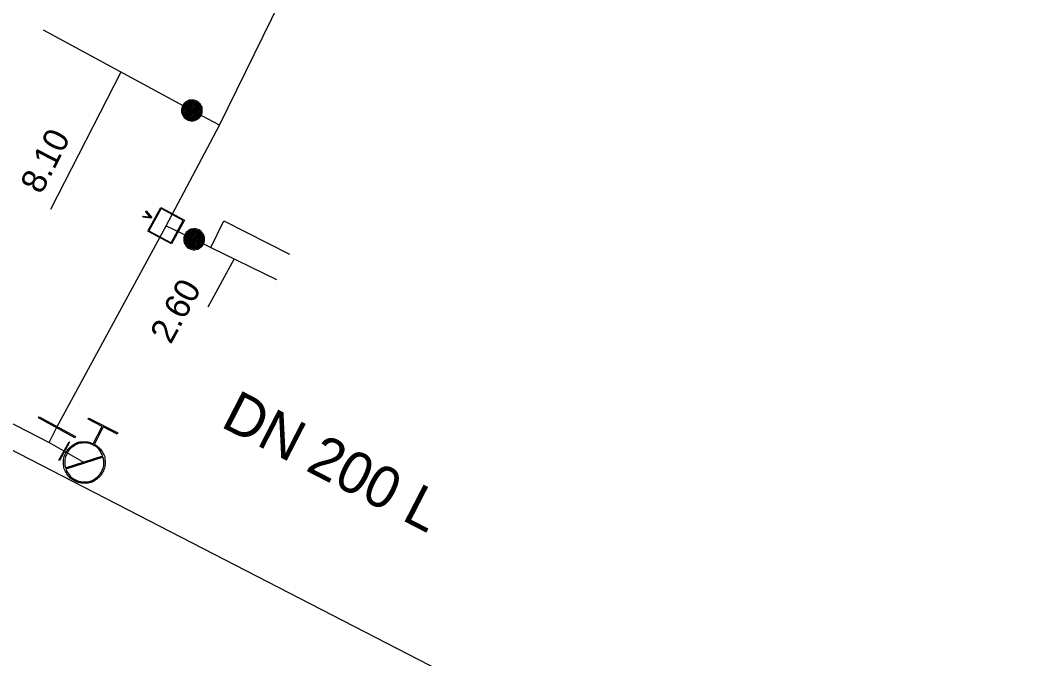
# Model space of a CAD drawing. Extents: x -820257 to -819974, y -1070894 to -1070484.
# Drawn here: x -820080.47 to -820031.98, y -1070577.38 to -1070546.62 of the extents above; entities that cross this region are included whole.
import ezdxf

# ---------------------------------------------------------------- set-up
doc = ezdxf.new("R2010")
doc.units = 0
for name, color, linetype in [('Hyd-odbočka', 7, 'Continuous'), ('Hyd-šoupě', 7, 'Continuous'), ('Hydrant', 7, 'Continuous'), ('Oměrka vodovodu', 7, 'Continuous'), ('Oměrka-text', 7, 'Continuous'), ('Přípojka vodovodu', 7, 'Continuous'), ('Přípojkový uzávěr', 7, 'Continuous'), ('Roz-řad', 7, 'Continuous'), ('Roz-řad-popis základní', 7, 'Continuous'), ('Řad-šoupě', 7, 'Continuous'), ('Šachta vodovodní', 7, 'Continuous')]:
    doc.layers.add(name, color=color, linetype=linetype)

msp = doc.modelspace()

# ---------------------------------------------------------------- linework, layer by layer
at = {"layer": 'Hyd-odbočka'}
msp.add_line((-820079.076, -1070566.966), (-820077.384, -1070567.92), dxfattribs=at)
at = {"layer": 'Hyd-šoupě'}
msp.add_lwpolyline([(-820078.091, -1070566.947), (-820078.582, -1070567.818), (-820078.609, -1070567.803), (-820078.118, -1070566.932), (-820078.091, -1070566.947)], dxfattribs=at)
at = {"layer": 'Hydrant'}
for points in [[(-820076.954, -1070567.017), (-820076.524, -1070566.183), (-820077.191, -1070565.84), (-820077.163, -1070565.784), (-820075.773, -1070566.499), (-820075.802, -1070566.555), (-820076.469, -1070566.212), (-820076.898, -1070567.045)], [(-820078.287, -1070568.177), (-820076.498, -1070567.605)], [(-820076.48, -1070567.663), (-820078.27, -1070568.237)]]:
    msp.add_lwpolyline(points, dxfattribs=at)
for points in [[(-820076.898, -1070567.045), (-820076.691, -1070567.16), (-820076.547, -1070567.371), (-820076.394, -1070567.595), (-820076.385, -1070567.87), (-820076.375, -1070568.145), (-820076.495, -1070568.378), (-820076.613, -1070568.609), (-820076.84, -1070568.76), (-820077.066, -1070568.912), (-820077.338, -1070568.92), (-820077.61, -1070568.928), (-820077.841, -1070568.809), (-820078.072, -1070568.69), (-820078.224, -1070568.464), (-820078.375, -1070568.238), (-820078.383, -1070567.965), (-820078.392, -1070567.693), (-820078.273, -1070567.462), (-820078.153, -1070567.229), (-820077.923, -1070567.078), (-820077.693, -1070566.926), (-820077.422, -1070566.92), (-820077.169, -1070566.914), (-820076.954, -1070567.017)], [(-820076.498, -1070567.605), (-820076.537, -1070567.499), (-820076.6, -1070567.405), (-820076.744, -1070567.195), (-820076.954, -1070567.086), (-820077.165, -1070566.978), (-820077.42, -1070566.983), (-820077.675, -1070566.988), (-820077.89, -1070567.13), (-820078.104, -1070567.272), (-820078.217, -1070567.491), (-820078.329, -1070567.708), (-820078.32, -1070567.963), (-820078.317, -1070568.074), (-820078.287, -1070568.177)], [(-820078.27, -1070568.237), (-820078.233, -1070568.337), (-820078.171, -1070568.429), (-820078.03, -1070568.642), (-820077.813, -1070568.753), (-820077.596, -1070568.865), (-820077.34, -1070568.857), (-820077.085, -1070568.849), (-820076.873, -1070568.708), (-820076.662, -1070568.566), (-820076.55, -1070568.349), (-820076.437, -1070568.13), (-820076.447, -1070567.873), (-820076.452, -1070567.762), (-820076.48, -1070567.663)]]:
    msp.add_open_spline(points, degree=3, dxfattribs=at)
at = {"layer": 'Oměrka vodovodu'}
for p, q in [((-820075.62, -1070549.122), (-820079.012, -1070555.738)), ((-820070.162, -1070558.11), (-820071.44, -1070560.435))]:
    msp.add_line(p, q, dxfattribs=at)
at = {"layer": 'Přípojka vodovodu'}
for p, q in [((-820071.289, -1070557.564), (-820070.668, -1070556.285)), ((-820070.668, -1070556.285), (-820067.503, -1070557.894))]:
    msp.add_line(p, q, dxfattribs=at)
for points in [[(-820070.878, -1070551.68), (-820072.198, -1070550.968), (-820079.355, -1070547.107)], [(-820073.442, -1070556.519), (-820072.092, -1070557.174), (-820071.289, -1070557.564), (-820068.118, -1070559.102)]]:
    msp.add_lwpolyline(points, dxfattribs=at)
at = {"layer": 'Přípojkový uzávěr'}
for points in [[(-820071.962, -1070550.528), (-820071.851, -1070550.588), (-820071.776, -1070550.701), (-820071.701, -1070550.815), (-820071.699, -1070550.953), (-820071.697, -1070551.091), (-820071.759, -1070551.206), (-820071.82, -1070551.32), (-820071.935, -1070551.394), (-820072.049, -1070551.467), (-820072.185, -1070551.469), (-820072.322, -1070551.47), (-820072.436, -1070551.408), (-820072.55, -1070551.347), (-820072.624, -1070551.232), (-820072.697, -1070551.118), (-820072.699, -1070550.982), (-820072.701, -1070550.846), (-820072.639, -1070550.731), (-820072.577, -1070550.616), (-820072.46, -1070550.542), (-820072.344, -1070550.468), (-820072.209, -1070550.468), (-820072.073, -1070550.468), (-820071.962, -1070550.528)], [(-820071.984, -1070550.569), (-820072.084, -1070550.515), (-820072.208, -1070550.515), (-820072.331, -1070550.515), (-820072.436, -1070550.582), (-820072.541, -1070550.649), (-820072.598, -1070550.754), (-820072.653, -1070550.857), (-820072.652, -1070550.98), (-820072.651, -1070551.103), (-820072.584, -1070551.207), (-820072.517, -1070551.311), (-820072.414, -1070551.367), (-820072.31, -1070551.423), (-820072.187, -1070551.422), (-820072.063, -1070551.42), (-820071.959, -1070551.354), (-820071.856, -1070551.287), (-820071.8, -1070551.184), (-820071.744, -1070551.079), (-820071.746, -1070550.954), (-820071.748, -1070550.829), (-820071.816, -1070550.726), (-820071.883, -1070550.624), (-820071.984, -1070550.569)], [(-820072, -1070550.599), (-820071.907, -1070550.65), (-820071.845, -1070550.745), (-820071.782, -1070550.839), (-820071.78, -1070550.955), (-820071.778, -1070551.071), (-820071.83, -1070551.168), (-820071.882, -1070551.264), (-820071.977, -1070551.325), (-820072.073, -1070551.387), (-820072.187, -1070551.388), (-820072.302, -1070551.389), (-820072.398, -1070551.337), (-820072.493, -1070551.285), (-820072.555, -1070551.189), (-820072.617, -1070551.093), (-820072.618, -1070550.979), (-820072.619, -1070550.866), (-820072.568, -1070550.77), (-820072.515, -1070550.673), (-820072.418, -1070550.611), (-820072.321, -1070550.549), (-820072.207, -1070550.549), (-820072.093, -1070550.549), (-820072, -1070550.599)], [(-820072.021, -1070550.638), (-820072.159, -1070550.564), (-820072.307, -1070550.609), (-820072.455, -1070550.654), (-820072.529, -1070550.791), (-820072.603, -1070550.927), (-820072.558, -1070551.076), (-820072.513, -1070551.225), (-820072.377, -1070551.298), (-820072.24, -1070551.372), (-820072.091, -1070551.328), (-820071.942, -1070551.283), (-820071.869, -1070551.147), (-820071.795, -1070551.01), (-820071.839, -1070550.861), (-820071.883, -1070550.713), (-820072.021, -1070550.638)], [(-820072.043, -1070550.678), (-820071.922, -1070550.743), (-820071.884, -1070550.873), (-820071.845, -1070551.003), (-820071.91, -1070551.123), (-820071.975, -1070551.243), (-820072.105, -1070551.282), (-820072.235, -1070551.32), (-820072.355, -1070551.256), (-820072.475, -1070551.191), (-820072.514, -1070551.061), (-820072.552, -1070550.931), (-820072.488, -1070550.811), (-820072.423, -1070550.691), (-820072.293, -1070550.652), (-820072.163, -1070550.613), (-820072.043, -1070550.678)], [(-820072.062, -1070550.713), (-820072.168, -1070550.656), (-820072.282, -1070550.69), (-820072.396, -1070550.725), (-820072.453, -1070550.83), (-820072.51, -1070550.935), (-820072.476, -1070551.05), (-820072.442, -1070551.164), (-820072.336, -1070551.221), (-820072.231, -1070551.278), (-820072.116, -1070551.244), (-820072.002, -1070551.209), (-820071.945, -1070551.104), (-820071.888, -1070550.999), (-820071.922, -1070550.885), (-820071.956, -1070550.77), (-820072.062, -1070550.713)], [(-820072.08, -1070550.748), (-820071.988, -1070550.798), (-820071.959, -1070550.897), (-820071.929, -1070550.996), (-820071.979, -1070551.087), (-820072.028, -1070551.179), (-820072.127, -1070551.208), (-820072.226, -1070551.238), (-820072.318, -1070551.188), (-820072.408, -1070551.139), (-820072.438, -1070551.04), (-820072.468, -1070550.941), (-820072.419, -1070550.85), (-820072.369, -1070550.759), (-820072.271, -1070550.729), (-820072.172, -1070550.698), (-820072.08, -1070550.748)], [(-820072.102, -1070550.789), (-820072.177, -1070550.749), (-820072.257, -1070550.773), (-820072.337, -1070550.797), (-820072.378, -1070550.871), (-820072.418, -1070550.946), (-820072.394, -1070551.026), (-820072.37, -1070551.106), (-820072.295, -1070551.146), (-820072.221, -1070551.186), (-820072.141, -1070551.162), (-820072.06, -1070551.138), (-820072.02, -1070551.064), (-820071.98, -1070550.99), (-820072.004, -1070550.909), (-820072.028, -1070550.829), (-820072.102, -1070550.789)], [(-820072.119, -1070550.819), (-820072.057, -1070550.853), (-820072.037, -1070550.919), (-820072.017, -1070550.986), (-820072.05, -1070551.048), (-820072.084, -1070551.11), (-820072.151, -1070551.129), (-820072.217, -1070551.149), (-820072.279, -1070551.116), (-820072.341, -1070551.083), (-820072.361, -1070551.016), (-820072.38, -1070550.95), (-820072.347, -1070550.888), (-820072.314, -1070550.826), (-820072.247, -1070550.806), (-820072.181, -1070550.786), (-820072.119, -1070550.819)], [(-820072.14, -1070550.858), (-820072.185, -1070550.834), (-820072.235, -1070550.848), (-820072.284, -1070550.863), (-820072.309, -1070550.909), (-820072.333, -1070550.955), (-820072.318, -1070551.004), (-820072.303, -1070551.054), (-820072.258, -1070551.078), (-820072.212, -1070551.103), (-820072.163, -1070551.088), (-820072.113, -1070551.073), (-820072.089, -1070551.028), (-820072.064, -1070550.982), (-820072.079, -1070550.933), (-820072.093, -1070550.883), (-820072.14, -1070550.858)], [(-820072.162, -1070550.899), (-820072.133, -1070550.915), (-820072.124, -1070550.946), (-820072.114, -1070550.976), (-820072.13, -1070551.005), (-820072.146, -1070551.034), (-820072.176, -1070551.043), (-820072.207, -1070551.053), (-820072.236, -1070551.037), (-820072.264, -1070551.022), (-820072.274, -1070550.99), (-820072.283, -1070550.959), (-820072.268, -1070550.931), (-820072.252, -1070550.902), (-820072.221, -1070550.893), (-820072.19, -1070550.884), (-820072.162, -1070550.899)], [(-820072.177, -1070550.927), (-820072.194, -1070550.918), (-820072.212, -1070550.923), (-820072.231, -1070550.928), (-820072.24, -1070550.946), (-820072.25, -1070550.963), (-820072.244, -1070550.982), (-820072.238, -1070551), (-820072.221, -1070551.009), (-820072.204, -1070551.019), (-820072.185, -1070551.013), (-820072.167, -1070551.008), (-820072.158, -1070550.99), (-820072.148, -1070550.973), (-820072.154, -1070550.955), (-820072.159, -1070550.936), (-820072.177, -1070550.927)], [(-820071.874, -1070556.724), (-820071.761, -1070556.779), (-820071.681, -1070556.89), (-820071.602, -1070557), (-820071.593, -1070557.138), (-820071.585, -1070557.275), (-820071.642, -1070557.393), (-820071.699, -1070557.51), (-820071.81, -1070557.588), (-820071.921, -1070557.666), (-820072.057, -1070557.674), (-820072.193, -1070557.681), (-820072.311, -1070557.624), (-820072.427, -1070557.568), (-820072.505, -1070557.456), (-820072.584, -1070557.345), (-820072.591, -1070557.209), (-820072.599, -1070557.073), (-820072.542, -1070556.957), (-820072.485, -1070556.839), (-820072.372, -1070556.76), (-820072.259, -1070556.681), (-820072.123, -1070556.675), (-820071.988, -1070556.669), (-820071.874, -1070556.724)], [(-820071.895, -1070556.767), (-820071.997, -1070556.717), (-820072.12, -1070556.722), (-820072.243, -1070556.727), (-820072.346, -1070556.799), (-820072.448, -1070556.87), (-820072.5, -1070556.977), (-820072.551, -1070557.083), (-820072.545, -1070557.206), (-820072.538, -1070557.329), (-820072.467, -1070557.43), (-820072.396, -1070557.531), (-820072.29, -1070557.582), (-820072.184, -1070557.633), (-820072.06, -1070557.627), (-820071.937, -1070557.62), (-820071.836, -1070557.549), (-820071.736, -1070557.479), (-820071.684, -1070557.373), (-820071.633, -1070557.266), (-820071.64, -1070557.141), (-820071.648, -1070557.016), (-820071.72, -1070556.916), (-820071.792, -1070556.816), (-820071.895, -1070556.767)], [(-820071.909, -1070556.797), (-820071.814, -1070556.844), (-820071.748, -1070556.936), (-820071.682, -1070557.028), (-820071.674, -1070557.143), (-820071.667, -1070557.259), (-820071.715, -1070557.358), (-820071.763, -1070557.456), (-820071.856, -1070557.521), (-820071.949, -1070557.587), (-820072.063, -1070557.593), (-820072.177, -1070557.599), (-820072.275, -1070557.551), (-820072.373, -1070557.504), (-820072.439, -1070557.41), (-820072.505, -1070557.317), (-820072.511, -1070557.204), (-820072.517, -1070557.09), (-820072.469, -1070556.992), (-820072.421, -1070556.893), (-820072.327, -1070556.827), (-820072.232, -1070556.761), (-820072.118, -1070556.756), (-820072.004, -1070556.751), (-820071.909, -1070556.797)], [(-820071.929, -1070556.837), (-820072.07, -1070556.768), (-820072.216, -1070556.82), (-820072.362, -1070556.871), (-820072.43, -1070557.011), (-820072.497, -1070557.151), (-820072.446, -1070557.297), (-820072.395, -1070557.444), (-820072.256, -1070557.511), (-820072.116, -1070557.58), (-820071.969, -1070557.529), (-820071.823, -1070557.478), (-820071.755, -1070557.339), (-820071.687, -1070557.198), (-820071.737, -1070557.052), (-820071.787, -1070556.905), (-820071.929, -1070556.837)], [(-820071.949, -1070556.878), (-820071.826, -1070556.938), (-820071.782, -1070557.066), (-820071.738, -1070557.194), (-820071.797, -1070557.316), (-820071.857, -1070557.439), (-820071.985, -1070557.483), (-820072.113, -1070557.528), (-820072.236, -1070557.468), (-820072.359, -1070557.409), (-820072.403, -1070557.281), (-820072.447, -1070557.152), (-820072.388, -1070557.03), (-820072.328, -1070556.907), (-820072.2, -1070556.863), (-820072.072, -1070556.818), (-820071.949, -1070556.878)], [(-820071.966, -1070556.913), (-820072.074, -1070556.861), (-820072.187, -1070556.9), (-820072.3, -1070556.94), (-820072.352, -1070557.047), (-820072.404, -1070557.155), (-820072.365, -1070557.268), (-820072.326, -1070557.38), (-820072.218, -1070557.433), (-820072.111, -1070557.485), (-820071.998, -1070557.446), (-820071.885, -1070557.407), (-820071.833, -1070557.299), (-820071.781, -1070557.191), (-820071.819, -1070557.079), (-820071.858, -1070556.966), (-820071.966, -1070556.913)], [(-820071.983, -1070556.949), (-820071.889, -1070556.995), (-820071.855, -1070557.093), (-820071.822, -1070557.19), (-820071.867, -1070557.284), (-820071.912, -1070557.377), (-820072.01, -1070557.411), (-820072.108, -1070557.445), (-820072.201, -1070557.399), (-820072.294, -1070557.354), (-820072.328, -1070557.256), (-820072.362, -1070557.159), (-820072.317, -1070557.066), (-820072.272, -1070556.972), (-820072.174, -1070556.938), (-820072.077, -1070556.904), (-820071.983, -1070556.949)], [(-820072.003, -1070556.991), (-820072.079, -1070556.954), (-820072.159, -1070556.982), (-820072.238, -1070557.009), (-820072.275, -1070557.085), (-820072.312, -1070557.161), (-820072.284, -1070557.24), (-820072.257, -1070557.32), (-820072.181, -1070557.356), (-820072.105, -1070557.393), (-820072.026, -1070557.366), (-820071.946, -1070557.338), (-820071.909, -1070557.262), (-820071.873, -1070557.186), (-820071.9, -1070557.107), (-820071.927, -1070557.028), (-820072.003, -1070556.991)], [(-820072.019, -1070557.022), (-820071.955, -1070557.053), (-820071.933, -1070557.118), (-820071.91, -1070557.184), (-820071.941, -1070557.247), (-820071.971, -1070557.311), (-820072.037, -1070557.333), (-820072.103, -1070557.356), (-820072.166, -1070557.325), (-820072.229, -1070557.295), (-820072.252, -1070557.229), (-820072.274, -1070557.163), (-820072.244, -1070557.1), (-820072.213, -1070557.037), (-820072.147, -1070557.014), (-820072.082, -1070556.991), (-820072.019, -1070557.022)], [(-820072.038, -1070557.062), (-820072.084, -1070557.039), (-820072.133, -1070557.056), (-820072.182, -1070557.073), (-820072.204, -1070557.12), (-820072.227, -1070557.166), (-820072.21, -1070557.215), (-820072.193, -1070557.264), (-820072.147, -1070557.287), (-820072.1, -1070557.309), (-820072.051, -1070557.292), (-820072.002, -1070557.276), (-820071.979, -1070557.229), (-820071.957, -1070557.182), (-820071.974, -1070557.134), (-820071.99, -1070557.085), (-820072.038, -1070557.062)], [(-820072.058, -1070557.104), (-820072.028, -1070557.118), (-820072.018, -1070557.148), (-820072.008, -1070557.178), (-820072.022, -1070557.208), (-820072.036, -1070557.237), (-820072.066, -1070557.248), (-820072.097, -1070557.259), (-820072.126, -1070557.244), (-820072.155, -1070557.23), (-820072.166, -1070557.2), (-820072.177, -1070557.169), (-820072.163, -1070557.14), (-820072.148, -1070557.11), (-820072.118, -1070557.1), (-820072.087, -1070557.09), (-820072.058, -1070557.104)], [(-820072.072, -1070557.132), (-820072.089, -1070557.123), (-820072.108, -1070557.13), (-820072.126, -1070557.136), (-820072.135, -1070557.154), (-820072.143, -1070557.171), (-820072.137, -1070557.19), (-820072.13, -1070557.208), (-820072.113, -1070557.216), (-820072.095, -1070557.225), (-820072.077, -1070557.219), (-820072.059, -1070557.212), (-820072.05, -1070557.195), (-820072.041, -1070557.177), (-820072.048, -1070557.159), (-820072.054, -1070557.141), (-820072.072, -1070557.132)]]:
    msp.add_open_spline(points, degree=3, dxfattribs=at)
at = {"layer": 'Roz-řad'}
for p, q in [((-820110.178, -1070552.224), (-820031.976, -1070592.492)), ((-820078.699, -1070566.224), (-820073.442, -1070556.519)), ((-820079.076, -1070566.966), (-820078.699, -1070566.224))]:
    msp.add_line(p, q, dxfattribs=at)
for points in [[(-820073.442, -1070556.519), (-820070.878, -1070551.68), (-820065.83, -1070541.39), (-820062.208, -1070534.681), (-820056.904, -1070524.441), (-820050.972, -1070512.997)], [(-820116.57, -1070529.663), (-820115.438, -1070530.28), (-820122.673, -1070544.495), (-820079.076, -1070566.966)]]:
    msp.add_lwpolyline(points, dxfattribs=at)
at = {"layer": 'Řad-šoupě'}
msp.add_lwpolyline([(-820079.563, -1070565.72), (-820077.805, -1070566.673), (-820077.835, -1070566.728), (-820079.593, -1070565.775), (-820079.563, -1070565.72)], dxfattribs=at)
at = {"layer": 'Šachta vodovodní'}
for points in [[(-820074.168, -1070556.154), (-820074.565, -1070556.103), (-820074.539, -1070556.056), (-820074.255, -1070556.099)], [(-820074.236, -1070556.064), (-820074.426, -1070555.848), (-820074.402, -1070555.803), (-820074.144, -1070556.109), (-820074.168, -1070556.154)], [(-820073.703, -1070555.637), (-820072.56, -1070556.256), (-820073.179, -1070557.399), (-820074.322, -1070556.78), (-820073.703, -1070555.637)], [(-820074.267, -1070556.764), (-820073.196, -1070557.344), (-820072.615, -1070556.273), (-820073.687, -1070555.692), (-820074.267, -1070556.764)]]:
    msp.add_lwpolyline(points, dxfattribs=at)
msp.add_open_spline([(-820074.255, -1070556.099), (-820074.221, -1070556.105), (-820074.193, -1070556.111), (-820074.215, -1070556.089), (-820074.236, -1070556.064)], degree=3, dxfattribs=at)

# ---------------------------------------------------------------- texts
at = {"layer": 'Oměrka-text'}
for s, rotation, p in [(' 8.10', 62.8559, (-820079.657, -1070555.446)), (' 2.60', 61.2064, (-820073.438, -1070562.66))]:
    msp.add_text(s, height=1.2, rotation=rotation, dxfattribs=at).set_placement(p)
at = {"layer": 'Roz-řad-popis základní'}
msp.add_text('DN 200 L', height=2, rotation=332.755, dxfattribs=at).set_placement((-820070.872, -1070566.17))

doc.saveas('drawing.dxf')
